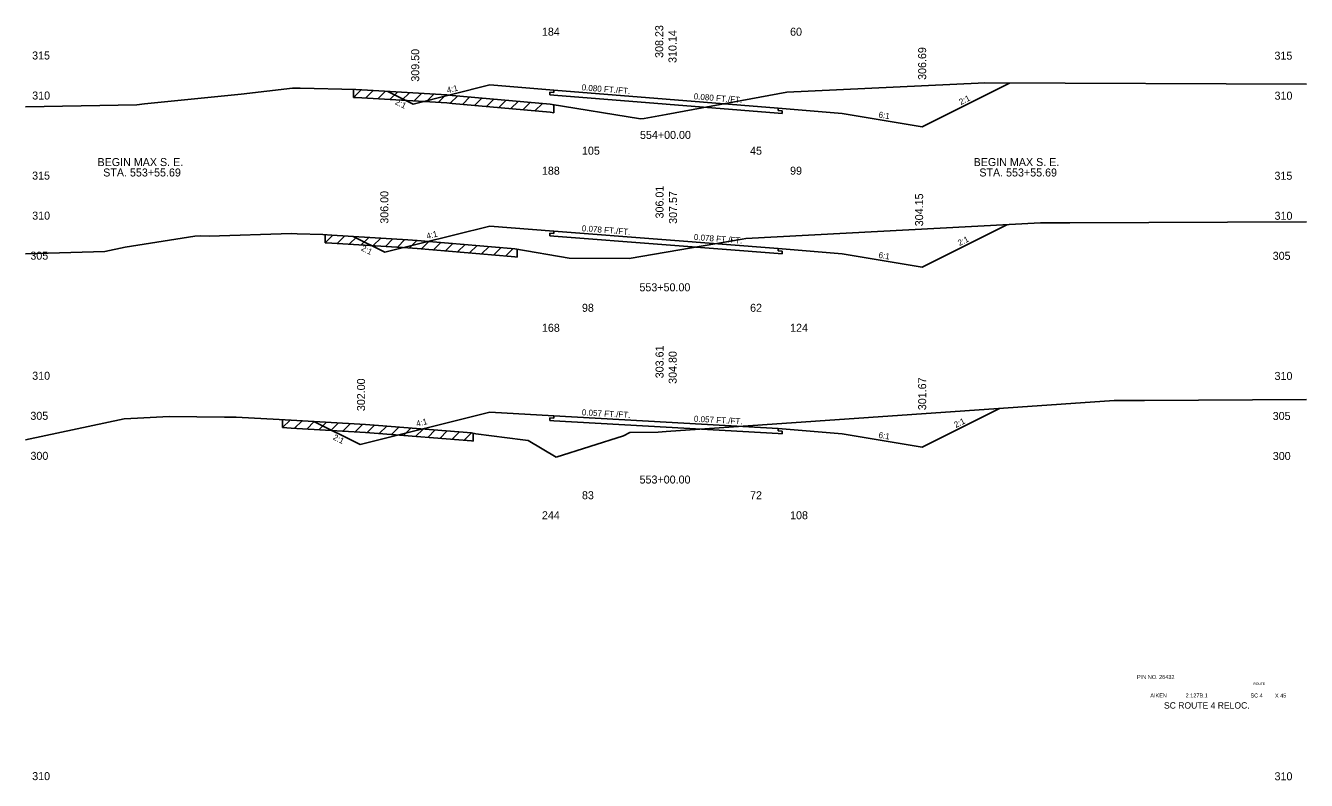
# Model space of a CAD drawing. Extents: x 2967 to 4323, y -3677 to -817.
# Drawn here: x 3555.3 to 3715.3, y -1404.8 to -1310.5 of the extents above; entities that cross this region are included whole.
import ezdxf

# ---------------------------------------------------------------- set-up
doc = ezdxf.new("R2010")
doc.units = 0
for name, color, linetype in [('Level 1', 7, 'Continuous'), ('Level 10', 7, 'Continuous'), ('Level 11', 7, 'Continuous'), ('Level 12', 7, 'Continuous'), ('Level 20', 7, 'Continuous'), ('Level 3', 7, 'Continuous'), ('Level 32', 7, 'Continuous'), ('Level 33', 7, 'Continuous'), ('Level 59', 7, 'Continuous'), ('Level 6', 7, 'Continuous'), ('Level 60', 7, 'Continuous'), ('Level 61', 7, 'Continuous'), ('Level 7', 7, 'Continuous')]:
    doc.layers.add(name, color=color, linetype=linetype)

msp = doc.modelspace()

# ---------------------------------------------------------------- linework, layer by layer
at = {"layer": 'Level 11'}
for p, q in [((3621.35, -1318.88), (3620.85, -1318.84)), ((3620.85, -1318.84), (3620.85, -1319.18)), ((3620.85, -1319.18), (3621.35, -1319.22)), ((3621.35, -1318.58), (3621.35, -1318.88)), ((3649.35, -1321.12), (3649.35, -1320.82)), ((3649.85, -1321.16), (3649.35, -1321.12)), ((3649.35, -1321.46), (3649.85, -1321.5)), ((3649.85, -1321.5), (3649.85, -1321.16)), ((3621.35, -1336.48), (3620.85, -1336.44)), ((3620.85, -1336.44), (3620.85, -1336.78)), ((3620.85, -1336.78), (3621.35, -1336.82)), ((3621.35, -1336.18), (3621.35, -1336.48)), ((3649.35, -1338.66), (3649.35, -1338.36)), ((3649.85, -1338.69), (3649.35, -1338.66)), ((3649.35, -1339), (3649.85, -1339.03)), ((3649.85, -1339.03), (3649.85, -1338.69)), ((3621.35, -1359.55), (3620.85, -1359.52)), ((3620.85, -1359.52), (3620.85, -1359.86)), ((3620.85, -1359.86), (3621.35, -1359.89)), ((3621.35, -1359.25), (3621.35, -1359.55)), ((3649.35, -1361.14), (3649.35, -1360.84)), ((3649.85, -1361.16), (3649.35, -1361.14)), ((3649.35, -1361.48), (3649.85, -1361.5)), ((3649.85, -1361.5), (3649.85, -1361.16))]:
    msp.add_line(p, q, dxfattribs=at)
at = {"layer": 'Level 12'}
for p, q in [((3635.35, -1320.34), (3621.35, -1319.22)), ((3649.35, -1321.46), (3635.35, -1320.34)), ((3635.35, -1337.91), (3621.35, -1336.82)), ((3649.35, -1339), (3635.35, -1337.91)), ((3635.35, -1360.68), (3621.35, -1359.89)), ((3649.35, -1361.48), (3635.35, -1360.68))]:
    msp.add_line(p, q, dxfattribs=at)
at = {"layer": 'Level 59'}
for p, q in [((3621.35, -1318.58), (3635.35, -1319.7)), ((3635.35, -1319.7), (3649.35, -1320.82)), ((3621.35, -1336.18), (3635.35, -1337.27)), ((3635.35, -1337.27), (3649.35, -1338.36)), ((3621.35, -1359.25), (3635.35, -1360.04)), ((3635.35, -1360.04), (3649.35, -1360.84))]:
    msp.add_line(p, q, dxfattribs=at)
at = {"layer": 'Level 6'}
for p, q in [((3613.35, -1317.94), (3621.35, -1318.58)), ((3649.35, -1320.82), (3657.35, -1321.49)), ((3613.35, -1335.56), (3621.35, -1336.18)), ((3649.35, -1338.36), (3657.35, -1339.02)), ((3613.35, -1358.79), (3621.35, -1359.25)), ((3649.35, -1360.84), (3657.35, -1361.5))]:
    msp.add_line(p, q, dxfattribs=at)
at = {"layer": 'Level 60'}
for p, q in [((3582.26, -1319.08), (3588.69, -1318.36)), ((3588.69, -1318.36), (3589.63, -1318.33)), ((3589.63, -1318.33), (3596.62, -1318.51)), ((3650.46, -1318.85), (3674.33, -1317.73)), ((3674.33, -1317.73), (3675.17, -1317.69)), ((3675.17, -1317.69), (3715.35, -1317.86)), ((3570.22, -1320.29), (3582.26, -1319.08)), ((3596.62, -1318.51), (3597.33, -1318.56)), ((3597.33, -1318.56), (3607.95, -1319.18)), ((3607.95, -1319.18), (3608.63, -1319.24)), ((3608.63, -1319.24), (3620.86, -1320.35)), ((3635.35, -1321.61), (3650.46, -1318.85)), ((3555.35, -1320.68), (3569.26, -1320.44)), ((3569.26, -1320.44), (3570.22, -1320.29)), ((3620.86, -1320.35), (3632.16, -1322.19)), ((3632.16, -1322.19), (3632.6, -1322.11)), ((3632.6, -1322.11), (3635.35, -1321.61)), ((3645.32, -1337.13), (3682.12, -1335.17)), ((3682.12, -1335.17), (3685.79, -1335.18)), ((3685.79, -1335.18), (3715.35, -1335.04)), ((3567.78, -1338.19), (3576.49, -1336.84)), ((3576.49, -1336.84), (3577.16, -1336.8)), ((3577.16, -1336.8), (3578.28, -1336.82)), ((3578.28, -1336.82), (3588.55, -1336.48)), ((3588.55, -1336.48), (3589.28, -1336.52)), ((3589.28, -1336.52), (3592.46, -1336.63)), ((3592.46, -1336.63), (3593.62, -1336.7)), ((3593.62, -1336.7), (3603.08, -1337.27)), ((3603.08, -1337.27), (3604.25, -1337.37)), ((3604.25, -1337.37), (3616, -1338.35)), ((3635.35, -1338.84), (3644.87, -1337.2)), ((3644.87, -1337.2), (3645.32, -1337.13)), ((3555.35, -1339.03), (3565.26, -1338.72)), ((3565.26, -1338.72), (3567.78, -1338.19)), ((3616, -1338.35), (3616.45, -1338.41)), ((3616.45, -1338.41), (3623.24, -1339.56)), ((3630.76, -1339.62), (3635.35, -1338.84)), ((3623.24, -1339.56), (3630.76, -1339.62)), ((3635.35, -1361.23), (3691.33, -1357.36)), ((3691.33, -1357.36), (3695.11, -1357.34)), ((3695.11, -1357.34), (3715.35, -1357.22)), ((3555.35, -1362.26), (3567.66, -1359.63)), ((3567.66, -1359.63), (3569.31, -1359.56)), ((3569.31, -1359.56), (3573.29, -1359.35)), ((3573.29, -1359.35), (3580.21, -1359.41)), ((3580.21, -1359.41), (3581.65, -1359.44)), ((3581.65, -1359.44), (3587.03, -1359.72)), ((3587.03, -1359.72), (3588.51, -1359.8)), ((3588.51, -1359.8), (3597.8, -1360.33)), ((3597.8, -1360.33), (3599.44, -1360.47)), ((3599.44, -1360.47), (3611.04, -1361.39)), ((3611.04, -1361.39), (3611.58, -1361.52)), ((3611.58, -1361.52), (3617.45, -1362.26)), ((3630.03, -1361.77), (3630.84, -1361.34)), ((3630.84, -1361.34), (3634.36, -1361.3)), ((3634.36, -1361.3), (3635.35, -1361.23)), ((3617.45, -1362.26), (3618.14, -1362.36)), ((3618.14, -1362.36), (3621.61, -1364.42)), ((3621.61, -1364.42), (3630.03, -1361.77))]:
    msp.add_line(p, q, dxfattribs=at)
at = {"layer": 'Level 61'}
for p, q in [((3596.31, -1318.51), (3596.31, -1319.51)), ((3597.27, -1318.55), (3596.31, -1319.51)), ((3596.31, -1319.51), (3596.62, -1319.51)), ((3596.62, -1319.51), (3597.33, -1319.56)), ((3597.33, -1319.56), (3607.95, -1320.18)), ((3598.78, -1318.64), (3597.82, -1319.59)), ((3600.29, -1318.73), (3599.34, -1319.68)), ((3601.8, -1318.82), (3600.85, -1319.76)), ((3603.31, -1318.91), (3602.36, -1319.85)), ((3604.82, -1319), (3603.87, -1319.94)), ((3606.33, -1319.09), (3605.38, -1320.03)), ((3607.84, -1319.18), (3606.89, -1320.12)), ((3609.33, -1319.3), (3608.4, -1320.22)), ((3610.84, -1319.44), (3609.91, -1320.36)), ((3612.35, -1319.58), (3611.43, -1320.49)), ((3613.86, -1319.71), (3612.94, -1320.63)), ((3615.37, -1319.85), (3614.45, -1320.77)), ((3616.88, -1319.99), (3615.96, -1320.9)), ((3607.95, -1320.18), (3608.63, -1320.24)), ((3608.63, -1320.24), (3620.86, -1321.35)), ((3618.39, -1320.12), (3617.47, -1321.04)), ((3619.91, -1320.26), (3618.98, -1321.18)), ((3620.86, -1321.35), (3621.34, -1321.42)), ((3621.34, -1321.42), (3621.34, -1320.42)), ((3592.76, -1336.65), (3592.76, -1337.65)), ((3593.71, -1336.7), (3592.76, -1337.65)), ((3595.21, -1336.8), (3594.27, -1337.74)), ((3596.72, -1336.89), (3595.77, -1337.83)), ((3598.22, -1336.98), (3597.28, -1337.92)), ((3599.73, -1337.07), (3598.78, -1338.01)), ((3601.23, -1337.16), (3600.29, -1338.1)), ((3602.74, -1337.25), (3601.79, -1338.19)), ((3604.22, -1337.37), (3603.29, -1338.29)), ((3605.72, -1337.49), (3604.8, -1338.41)), ((3592.76, -1337.65), (3593.62, -1337.7)), ((3593.62, -1337.7), (3603.08, -1338.27)), ((3603.08, -1338.27), (3604.25, -1338.37)), ((3604.25, -1338.37), (3616, -1339.35)), ((3607.23, -1337.62), (3606.3, -1338.54)), ((3608.73, -1337.74), (3607.81, -1338.67)), ((3610.24, -1337.87), (3609.31, -1338.79)), ((3611.74, -1338), (3610.82, -1338.92)), ((3613.25, -1338.12), (3612.32, -1339.04)), ((3614.75, -1338.25), (3613.82, -1339.17)), ((3616.24, -1338.38), (3615.33, -1339.3)), ((3616.75, -1339.46), (3616.75, -1338.46)), ((3616, -1339.35), (3616.45, -1339.41)), ((3616.45, -1339.41), (3616.75, -1339.46)), ((3587.43, -1359.74), (3587.43, -1360.74)), ((3588.39, -1359.79), (3587.43, -1360.74)), ((3589.9, -1359.88), (3588.94, -1360.82)), ((3591.41, -1359.96), (3590.46, -1360.91)), ((3587.43, -1360.74), (3588.51, -1360.8)), ((3588.51, -1360.8), (3597.8, -1361.33)), ((3592.92, -1360.05), (3591.97, -1361)), ((3594.43, -1360.14), (3593.48, -1361.08)), ((3595.95, -1360.22), (3594.99, -1361.17)), ((3597.46, -1360.31), (3596.5, -1361.26)), ((3597.8, -1361.33), (3599.44, -1361.47)), ((3598.95, -1360.43), (3598.02, -1361.35)), ((3599.44, -1361.47), (3611.04, -1362.39)), ((3600.46, -1360.55), (3599.53, -1361.48)), ((3601.97, -1360.67), (3601.04, -1361.6)), ((3603.49, -1360.79), (3602.55, -1361.72)), ((3605, -1360.91), (3604.07, -1361.84)), ((3606.51, -1361.03), (3605.58, -1361.96)), ((3608.02, -1361.15), (3607.09, -1362.08)), ((3609.54, -1361.27), (3608.6, -1362.2)), ((3611.05, -1361.4), (3610.12, -1362.32)), ((3611.24, -1362.44), (3611.24, -1361.44)), ((3611.04, -1362.39), (3611.24, -1362.44))]:
    msp.add_line(p, q, dxfattribs=at)
at = {"layer": 'Level 7'}
for p, q in [((3613.35, -1317.94), (3603.76, -1320.34)), ((3667.35, -1323.15), (3678.25, -1317.7)), ((3600.59, -1318.75), (3603.76, -1320.34)), ((3657.35, -1321.49), (3667.35, -1323.15)), ((3613.35, -1335.56), (3600.22, -1338.84)), ((3667.35, -1340.69), (3677.93, -1335.4)), ((3600.22, -1338.84), (3596.26, -1336.86)), ((3657.35, -1339.02), (3667.35, -1340.69)), ((3667.35, -1363.17), (3676.99, -1358.35)), ((3597.13, -1362.85), (3591.36, -1359.96)), ((3613.35, -1358.79), (3597.13, -1362.85)), ((3657.35, -1361.5), (3667.35, -1363.17))]:
    msp.add_line(p, q, dxfattribs=at)

# ---------------------------------------------------------------- texts
at = {"layer": 'Level 1'}
for s, p in [('184', (3619.85, -1311.79)), ('60', (3650.85, -1311.79)), ('105', (3624.85, -1326.65)), ('45', (3645.85, -1326.65)), ('BEGIN MAX S. E.', (3564.33, -1328.07)), ('BEGIN MAX S. E.', (3673.78, -1328.07)), ('STA. 553+55.69', (3565.04, -1329.37)), ('188', (3619.85, -1329.15)), ('99', (3650.85, -1329.15)), ('STA. 553+55.69', (3674.49, -1329.37)), ('98', (3624.85, -1346.27)), ('62', (3645.85, -1346.27)), ('168', (3619.85, -1348.77)), ('124', (3650.85, -1348.77)), ('83', (3624.85, -1369.68)), ('72', (3645.85, -1369.68)), ('244', (3619.85, -1372.18)), ('108', (3650.85, -1372.18))]:
    msp.add_text(s, height=1, dxfattribs=at).set_placement(p)
at = {"layer": 'Level 10'}
for s, p in [('308.23', (3635, -1314.56)), ('306.01', (3635.04, -1334.61)), ('303.61', (3635.04, -1354.57))]:
    msp.add_text(s, height=1, rotation=90, dxfattribs=at).set_placement(p)
for s, p in [('554+00.00', (3632.1, -1324.68)), ('553+50.00', (3632.03, -1343.71)), ('553+00.00', (3632.05, -1367.72))]:
    msp.add_text(s, height=1, dxfattribs=at).set_placement(p)
at = {"layer": 'Level 20'}
for s, height, p in [('PIN NO. 26432', 0.5, (3694.19, -1392.13)), ('ROUTE', 0.3, (3708.73, -1392.88)), ('AIKEN', 0.5, (3695.85, -1394.44)), ('SC ROUTE 4 RELOC.', 0.8, (3697.56, -1395.83)), (' 2.127B.1', 0.5, (3700.07, -1394.44)), ('SC 4', 0.5, (3708.36, -1394.44)), ('X 45', 0.5, (3711.42, -1394.46))]:
    msp.add_text(s, height=height, dxfattribs=at).set_placement(p)
at = {"layer": 'Level 3'}
for s, p in [(' 315', (3555.79, -1314.76)), (' 315', (3710.99, -1314.78)), (' 310', (3555.8, -1319.76)), (' 310', (3711, -1319.78)), (' 315', (3555.79, -1329.76)), (' 315', (3710.99, -1329.78)), (' 310', (3555.8, -1334.76)), (' 310', (3711, -1334.78)), (' 305', (3555.57, -1339.76)), (' 305', (3710.77, -1339.78)), (' 310', (3555.8, -1354.76)), (' 310', (3711, -1354.78)), (' 305', (3555.57, -1359.76)), (' 305', (3710.77, -1359.78)), (' 300', (3555.58, -1364.76)), (' 300', (3710.78, -1364.78)), (' 310', (3555.8, -1404.76)), (' 310', (3711, -1404.78))]:
    msp.add_text(s, height=1, dxfattribs=at).set_placement(p)
at = {"layer": 'Level 32'}
for s, rotation, p in [('4:1', 14.0362, (3608.06, -1318.98)), ('0.080 FT./FT.', 355.4261, (3624.79, -1318.6)), ('2:1', 333.435, (3601.42, -1320.31)), ('0.080 FT./FT.', 355.4261, (3638.79, -1319.72)), ('2:1', 26.5651, (3672.18, -1320.46)), ('6:1', 350.5377, (3661.86, -1321.99)), ('0.078 FT./FT.', 355.561, (3624.81, -1336.2)), ('4:1', 14.0362, (3605.51, -1337.2)), ('0.078 FT./FT.', 355.5612, (3638.81, -1337.29)), ('2:1', 26.5651, (3672.02, -1338.07)), ('2:1', 333.435, (3597.18, -1338.57)), ('6:1', 350.5377, (3661.86, -1339.52)), ('4:1', 14.0362, (3604.24, -1360.63)), ('0.057 FT./FT.', 356.7489, (3624.82, -1359.19)), ('0.057 FT./FT.', 356.7501, (3638.82, -1359.99)), ('2:1', 26.5651, (3671.55, -1360.79)), ('2:1', 333.435, (3593.67, -1362.18)), ('6:1', 350.5377, (3661.86, -1362))]:
    msp.add_text(s, height=0.75, rotation=rotation, dxfattribs=at).set_placement(p)
at = {"layer": 'Level 33'}
for s, p in [('309.50', (3604.52, -1317.53)), ('306.69', (3667.85, -1317.31)), ('306.00', (3600.66, -1335.27)), ('304.15', (3667.47, -1335.59)), ('302.00', (3597.75, -1358.68)), ('301.67', (3667.85, -1358.56))]:
    msp.add_text(s, height=1, rotation=90, dxfattribs=at).set_placement(p)
at = {"layer": 'Level 59'}
for s, p in [(' 310.14', (3636.66, -1315.56)), (' 307.57', (3636.72, -1335.66)), (' 304.80', (3636.68, -1355.64))]:
    msp.add_text(s, height=1, rotation=90, dxfattribs=at).set_placement(p)

doc.saveas('drawing.dxf')
